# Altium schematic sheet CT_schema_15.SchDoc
size 147 x 119 mm
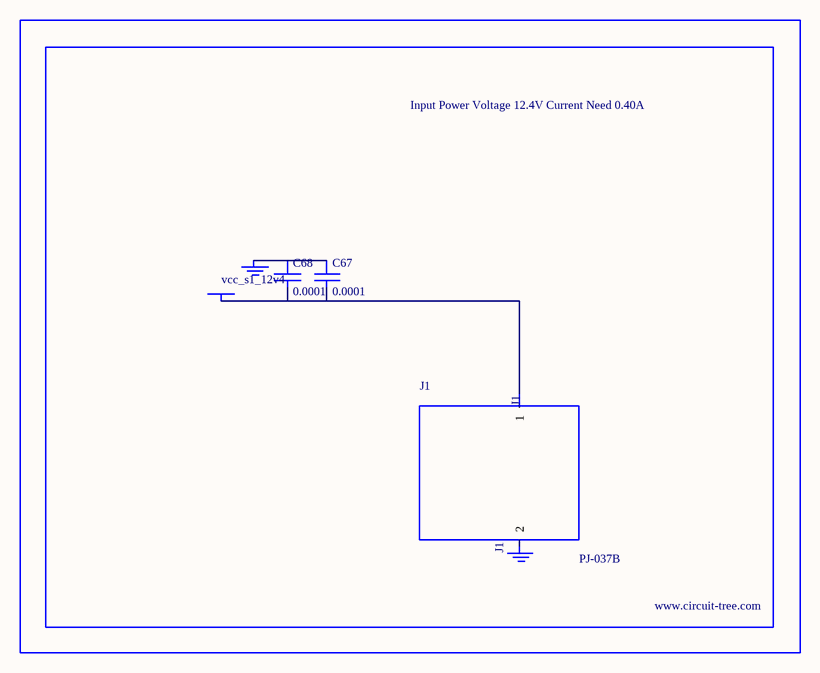
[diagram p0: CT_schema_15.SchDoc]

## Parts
BORDER14  (no value)
C67  0.0001  [EXV-9H]
C68  0.0001  [EXV-9H]
GND_INSTANCE_14_0  (no value)
GND_INSTANCE_14_1  (no value)
J1  PJ-037B  [PJ-037B_PACKAGE]
POWER_INSTANCE_14_0  vcc_s1_12v4

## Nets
NetC67_1: C67.1 C68.1 GND_INSTANCE_14_0.0(GND)
NetC67_2: C67.2 C68.2 J1.1 POWER_INSTANCE_14_0.0(PWR)

Not connected (* = marked no-connect by the designer): GND_INSTANCE_14_1 0(GND); J1 2

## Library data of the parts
BORDER14 = BORDER_PAGE14
C67 C68 = EDK107M035A9HAA
GND_INSTANCE_14_0 GND_INSTANCE_14_1 = GND
POWER_INSTANCE_14_0 = PWR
